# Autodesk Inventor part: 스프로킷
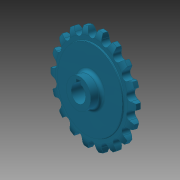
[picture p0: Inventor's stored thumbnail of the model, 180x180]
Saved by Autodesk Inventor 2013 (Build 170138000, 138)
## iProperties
Created: 2016-03
Part Number: 스프로킷
Material: 강철, 탄소
Document SubType Name: Modeling
Designer: mduedu
Density: 7.87 g/cm^3
Mass: 301.818 g
Surface Area: 124.882 cm^2
Volume: 38.3505 cm^3
Author: mduedu
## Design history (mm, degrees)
sketch "스케치1"
  geometry: L1 (0, 5)-(33.5, 5); L2 (33.5, 5)-(33.5, 4.1); L3 (34, 3.6)-(37.625, 3.6); L4 (44, 2)-(44, 0); L5 (44, 0)-(0, 0); L6 (0, 0)-(0, 5); L7 (0, -5)-(33.5, -5); L8 (33.5, -5)-(33.5, -4.1); L9 (34, -3.6)-(37.625, -3.6); L10 (44, -2)-(44, 0); L11 (0, 0)-(0, -5); A1 r 13.5 centre (37.625, -9.9) between (44, 2) and (37.625, 3.6); A2 r 13.5 centre (37.625, 9.9) between (37.625, -3.6) and (44, -2); A3 r 0.5 centre (34, 4.1) between (33.5, 4.1) and (34, 3.6); A4 r 0.5 centre (34, -4.1) between (34, -3.6) and (33.5, -4.1); 2 further points
  constraints: 22 end point, 8 point on circle, 6 symmetric about line, 5 tangent, 4 centre point, 4 parallel, 4 point on line, 1 equal radius, 1 horizontal, 1 perpendicular, 1 other
  dimensions: "d0" = 88 diameter of L4 L6; "d2" = 67 diameter of L2 L6; "d3" = 1.6 vertical distance of L4.start L3.end; "d4" = 3.6 distance from line of L4.end L3; "d5" = 5 distance between parallel lines of L5 L1; "d6" = 13.5 radius of A1; "d15" = 0.5 radius of A3
revolve "회전1" sketch "스케치1" stored, may be unused: angle "d7" = 90 deg
sketch "스케치2" dims "d8" = 73.24, "d11" = 88
  geometry: L1 (0, 0)-(0, 36.62); A1 r 40.59 centre (0, 0) between (-16.315, 37.167) and (0, 40.59); A2 r 3.97 centre (0, 40.59) between (-3.885, 39.775) and (0, 36.62); A3 r 12.7 centre (-16.315, 37.167) between (-3.885, 39.775) and (-5.404, 43.667); A4 r 12.7 centre (16.315, 37.167) between (5.404, 43.667) and (3.885, 39.775); A5 r 3.97 centre (0, 40.59) between (0, 36.62) and (3.885, 39.775); A6 r 44 centre (0, 0) between (5.404, 43.667) and (-5.404, 43.667); 2 further points
  constraints: 12 point on circle, 6 centre point, 4 coincident, 3 symmetric about line, 2 end point, 1 point on line, 1 tangent, 1 vertical, 1 vertical alignment, 7 other
  dimensions: "d10" = 81.18 diameter of A1; "d12" = 12.7 radius of A3
extrude "돌출1" cut sketch "스케치2" stored distance "d13" = 10; taper "d14" = 0 deg
sketch "스케치3"
  geometry: C1 r 12.5 at (0, 0); 1 further point
  constraints: 1 centre point, 1 coincident
  dimensions: "d19" = 25 diameter of C1
extrude "돌출2" join sketch "스케치3" distance "d20" = 10; taper "d21" = 0 deg
fillet "모깎기1" dims "d22" = 3
sketch "스케치4"
  geometry: L1 (-2.5, 0)-(2.5, 0); L2 (2.5, 0)-(2.5, 9.8); L3 (2.5, 9.8)-(-2.5, 9.8); L4 (-2.5, 9.8)-(-2.5, 0); C1 r 7.5 at (0, 0); 2 further points
  constraints: 8 end point, 2 coincident, 2 parallel, 1 centre point, 1 horizontal, 1 midpoint, 1 perpendicular
  dimensions: "d23" = 15 diameter of C1; "d25" = 5 distance of L2.end L3.end; "d26" = 9.8 distance of L1.end L2.end
extrude "돌출3" cut sketch "스케치4" stored distance "d27" = 8; taper "d28" = 0 deg
node "솔리드1"
pattern_circular "원형 패턴1" dims angle "d17" = 360 deg
